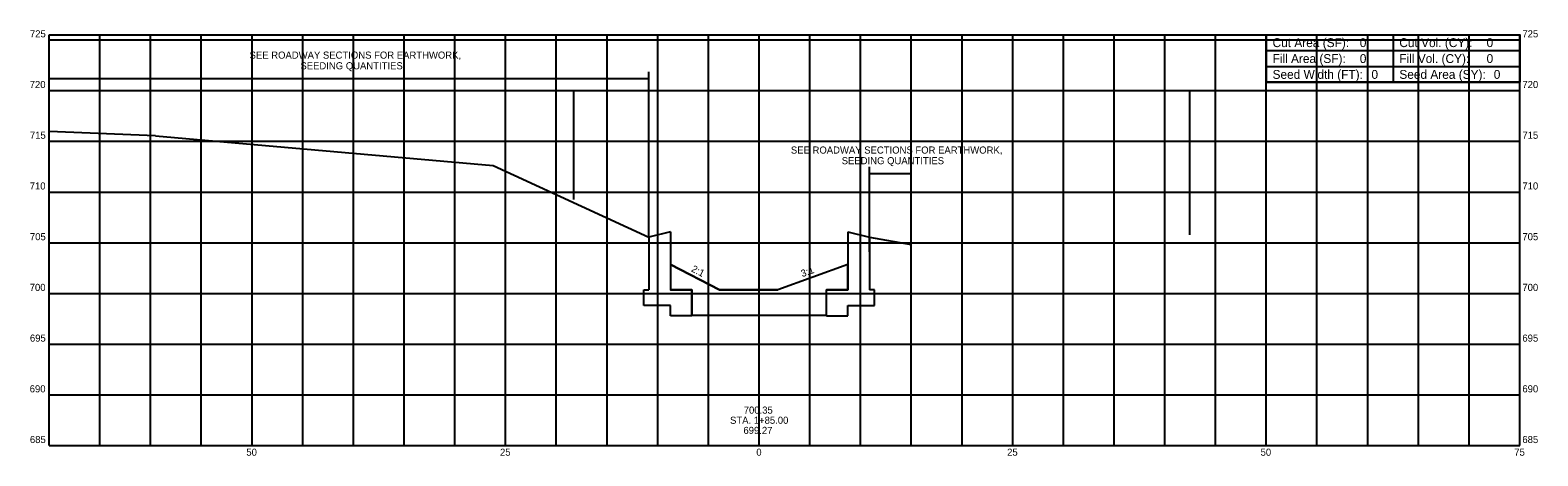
# Model space of a CAD drawing. Extents: x -72 to 77, y 684 to 726.
import ezdxf

# ---------------------------------------------------------------- set-up
doc = ezdxf.new("R2010")
doc.units = 0
for name, color, linetype in [('DR_P_Erosion_Control', 7, 'Continuous'), ('DR_P_Headwall', 7, 'Continuous'), ('MD_P_Surface_Finished_Grade', 7, 'Continuous'), ('PV_P_Shoulder', 7, 'Continuous'), ('SG_P_Manhole', 7, 'Continuous'), ('SH_Data', 7, 'Continuous'), ('SH_Major_Grid_Line', 7, 'Continuous'), ('SH_Text', 7, 'Continuous')]:
    doc.layers.add(name, color=color, linetype=linetype)

msp = doc.modelspace()

# ---------------------------------------------------------------- linework, layer by layer
at = {"layer": 'DR_P_Erosion_Control'}
for p, q in [((-8.75, 702.85), (-3.92, 700.35)), ((8.75, 702.85), (1.85, 700.35)), ((-3.92, 700.35), (1.85, 700.35)), ((-6.63, 697.85), (6.63, 697.85))]:
    msp.add_line(p, q, dxfattribs=at)
msp.add_lwpolyline([(-8.75, 702.85), (-8.75, 700.35), (-6.63, 700.35), (-6.63, 697.85), (6.63, 697.85), (6.63, 700.35), (8.75, 700.35), (8.75, 702.85), (1.85, 700.35), (-3.92, 700.35)], close=True, dxfattribs=at)
at = {"layer": 'DR_P_Headwall'}
for p, q in [((-8.75, 706.07), (-10.87, 705.55)), ((-10.87, 705.55), (-10.87, 700.35)), ((-8.75, 706.07), (-8.75, 700.35)), ((8.75, 706.07), (10.87, 705.55)), ((8.75, 706.07), (8.75, 700.35)), ((10.87, 705.55), (10.87, 700.35)), ((-11.36, 698.81), (-11.36, 700.35)), ((-11.36, 700.35), (-10.87, 700.35)), ((-6.63, 700.35), (-8.75, 700.35)), ((-6.63, 697.81), (-6.63, 700.35)), ((6.63, 697.81), (6.63, 700.35)), ((8.75, 700.35), (6.63, 700.35)), ((11.36, 700.35), (10.87, 700.35)), ((11.36, 698.81), (11.36, 700.35)), ((-8.75, 698.81), (-11.36, 698.81)), ((-8.75, 697.81), (-8.75, 698.81)), ((8.75, 698.81), (11.36, 698.81)), ((8.75, 697.81), (8.75, 698.81)), ((-6.63, 697.81), (-8.75, 697.81)), ((6.63, 697.81), (8.75, 697.81))]:
    msp.add_line(p, q, dxfattribs=at)
at = {"layer": 'MD_P_Surface_Finished_Grade'}
for p, q in [((42.47, 705.77), (42.47, 720)), ((-59.53, 715.55), (-70, 715.96)), ((-59.53, 715.55), (-26.24, 712.62)), ((-26.24, 712.62), (-10.87, 705.55)), ((10.87, 705.55), (15, 704.84))]:
    msp.add_line(p, q, dxfattribs=at)
at = {"layer": 'PV_P_Shoulder'}
msp.add_lwpolyline([(50, 725.51), (75, 725.51), (75, 720.82), (50, 720.82)], close=True, dxfattribs=at)
at = {"layer": 'SG_P_Manhole'}
msp.add_line((-18.27, 709.25), (-18.27, 720), dxfattribs=at)
at = {"layer": 'SH_Data'}
for p, q in [((50, 725.51), (75, 725.51)), ((50, 725.51), (50, 722.38)), ((62.5, 725.51), (62.5, 720.82)), ((75, 725.51), (75, 722.38)), ((50, 723.94), (75, 723.94)), ((50, 722.38), (75, 722.38))]:
    msp.add_line(p, q, dxfattribs=at)
msp.add_lwpolyline([(50, 722.38), (50, 720.82), (75, 720.82), (75, 722.38)], dxfattribs=at)
at = {"layer": 'SH_Major_Grid_Line'}
for p, q in [((-70, 725.51), (75, 725.51)), ((-70, 685), (-70, 725.51)), ((-65, 685), (-65, 725.51)), ((-60, 685), (-60, 725.51)), ((-55, 685), (-55, 725.51)), ((-50, 685), (-50, 725.51)), ((-45, 685), (-45, 725.51)), ((-40, 685), (-40, 725.51)), ((-35, 685), (-35, 725.51)), ((-30, 685), (-30, 725.51)), ((-25, 685), (-25, 725.51)), ((-20, 685), (-20, 725.51)), ((-15, 685), (-15, 725.51)), ((-10, 685), (-10, 725.51)), ((-5, 685), (-5, 725.51)), ((0, 685), (0, 725.51)), ((5, 685), (5, 725.51)), ((10, 685), (10, 725.51)), ((15, 685), (15, 725.51)), ((20, 685), (20, 725.51)), ((25, 685), (25, 725.51)), ((30, 685), (30, 725.51)), ((35, 685), (35, 725.51)), ((40, 685), (40, 725.51)), ((45, 685), (45, 725.51)), ((50, 685), (50, 725.51)), ((55, 685), (55, 725.51)), ((60, 685), (60, 725.51)), ((65, 685), (65, 725.51)), ((70, 685), (70, 725.51)), ((75, 685), (75, 725.51)), ((-70, 725), (75, 725)), ((-70, 720), (75, 720)), ((-70, 715), (75, 715)), ((-70, 710), (75, 710)), ((-70, 705), (75, 705)), ((-70, 700), (75, 700)), ((-70, 695), (75, 695)), ((-70, 690), (75, 690)), ((-70, 685), (75, 685))]:
    msp.add_line(p, q, dxfattribs=at)
at = {"layer": 'SH_Text'}
for p, q in [((-70, 721.2), (-10.87, 721.2)), ((-10.87, 705.55), (-10.87, 721.85)), ((10.87, 704.12), (10.87, 712.48)), ((15, 704.84), (15, 712.48)), ((10.87, 711.83), (15, 711.83))]:
    msp.add_line(p, q, dxfattribs=at)

# ---------------------------------------------------------------- texts
for s, height, p in [('725', 0.7, (-71.9, 725.25)), ('725', 0.7, (75.25, 725.25)), ('Cut Area (SF):', 0.875, (50.62, 724.29)), ('0', 0.875, (59.22, 724.29)), ('Cut Vol. (CY):', 0.875, (63.12, 724.29)), ('0', 0.875, (71.72, 724.29)), ('SEE ROADWAY SECTIONS FOR EARTHWORK,', 0.7, (-50.24, 723.15)), (' SEEDING QUANTITIES ', 0.7, (-45.49, 722.1)), ('Fill Area (SF):', 0.875, (50.62, 722.72)), ('0', 0.875, (59.22, 722.72)), ('Fill Vol. (CY):', 0.875, (63.12, 722.72)), ('0', 0.875, (71.72, 722.72)), ('720', 0.7, (-71.92, 720.25)), ('Seed Width (FT):', 0.875, (50.62, 721.16)), ('0', 0.875, (60.37, 721.16)), ('Seed Area (SY):', 0.875, (63.12, 721.16)), ('0', 0.875, (72.43, 721.16)), ('720', 0.7, (75.25, 720.25)), ('715', 0.7, (-71.9, 715.25)), ('715', 0.7, (75.25, 715.25)), ('SEE ROADWAY SECTIONS FOR EARTHWORK,', 0.7, (3.13, 713.79)), (' SEEDING QUANTITIES ', 0.7, (7.88, 712.74)), ('710', 0.7, (-71.92, 710.25)), ('710', 0.7, (75.25, 710.25)), ('705', 0.7, (-71.9, 705.25)), ('705', 0.7, (75.25, 705.25)), ('700', 0.7, (-71.92, 700.25)), ('700', 0.7, (75.25, 700.25)), ('695', 0.7, (-71.9, 695.25)), ('695', 0.7, (75.25, 695.25)), ('690', 0.7, (-71.92, 690.25)), ('690', 0.7, (75.25, 690.25)), ('700.35', 0.7, (-1.52, 688.15)), ('STA. 1+85.00', 0.7, (-2.87, 687.15)), ('699.27', 0.7, (-1.55, 686.15)), ('685', 0.7, (-71.9, 685.25)), ('685', 0.7, (75.25, 685.25)), ('50', 0.7, (-50.56, 684)), ('25', 0.7, (-25.55, 684)), ('0', 0.7, (-0.28, 684)), ('25', 0.7, (24.45, 684)), ('50', 0.7, (49.44, 684)), ('75', 0.7, (74.45, 684))]:
    msp.add_text(s, height=height, dxfattribs=at).set_placement(p)
for s, rotation, p in [('2:1', 332.634, (-6.76, 702.21)), ('3:1', 19.9164, (4.26, 701.6))]:
    msp.add_text(s, height=0.7, rotation=rotation, dxfattribs=at).set_placement(p)

doc.saveas('drawing.dxf')
